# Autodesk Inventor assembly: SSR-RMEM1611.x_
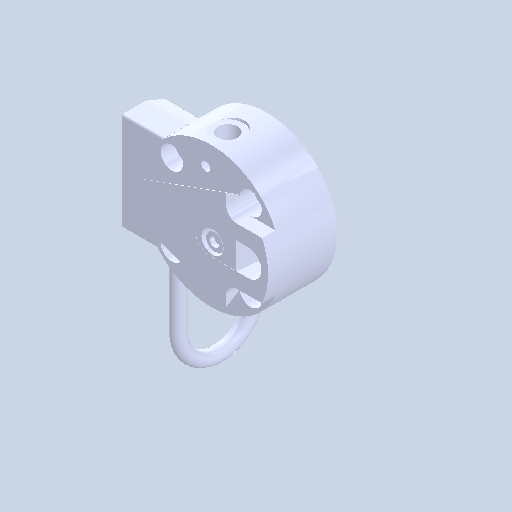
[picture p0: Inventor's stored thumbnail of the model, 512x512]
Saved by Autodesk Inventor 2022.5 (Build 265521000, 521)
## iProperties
Created: 2024-09
Part Number: SSR-RMEM1611.x_
Document SubType Name: Assembly
Designer: ImaoCorp
Author: ImaoCorp
Sending System: SOLIDWORKS 2022-2022290
MC: AMD64
MC_MODEL: Intel64 Family 6 Model 60 Stepping 3, GenuineIntel
OS: Windows_NT
FRU: Parasolid Version 33.1, build 260,  4-25-2022
FORMAT: text
GUISE: transmit
KEY: FILESSR-RMEM1611.x_t
DATE: Wed Sep 11 11:57:15 2024
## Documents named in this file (3)
- Y:\5.更新分\2024年対応\0911_SSR-RM\ssr-rmem1611\SSR-RMEM1611.x_.iam
- Y:\5.更新分\2024年対応\0911_SSR-RM\ssr-rmem1611\SSR-RMEM1611_01.ipt
- Y:\5.更新分\2024年対応\0911_SSR-RM\ssr-rmem1611\SSR-RMEM1611_02.ipt
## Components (2 placed, 2 different names)
1. SSR-RMEM1611_01
2. SSR-RMEM1611_02
